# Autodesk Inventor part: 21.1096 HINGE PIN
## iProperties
Created: 2007-01
Part Number: 21.1096 HINGE PIN
Document SubType Name: Modeling
Designer: Andy Moles
Material: Steel
Mass: 14.1209 g
Surface Area: 12.6359 cm^2
Volume: 1.79884 cm^3
Density: 7.85 g/cm^3
Author: Andy Moles
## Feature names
1. Extrusion1
2. Chamfer1
3. Chamfer2
4. Extrusion2
5. Extrusion3
6. Circular Pattern1
